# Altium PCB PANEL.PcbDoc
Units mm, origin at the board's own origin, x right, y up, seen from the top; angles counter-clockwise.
Board outline 203 x 188 mm, 4 copper layers (TOP, GND, SIG, BOTTOM), stack 1.586 mm thick; 0 components, 0 nets, 13 pads, 0 vias.
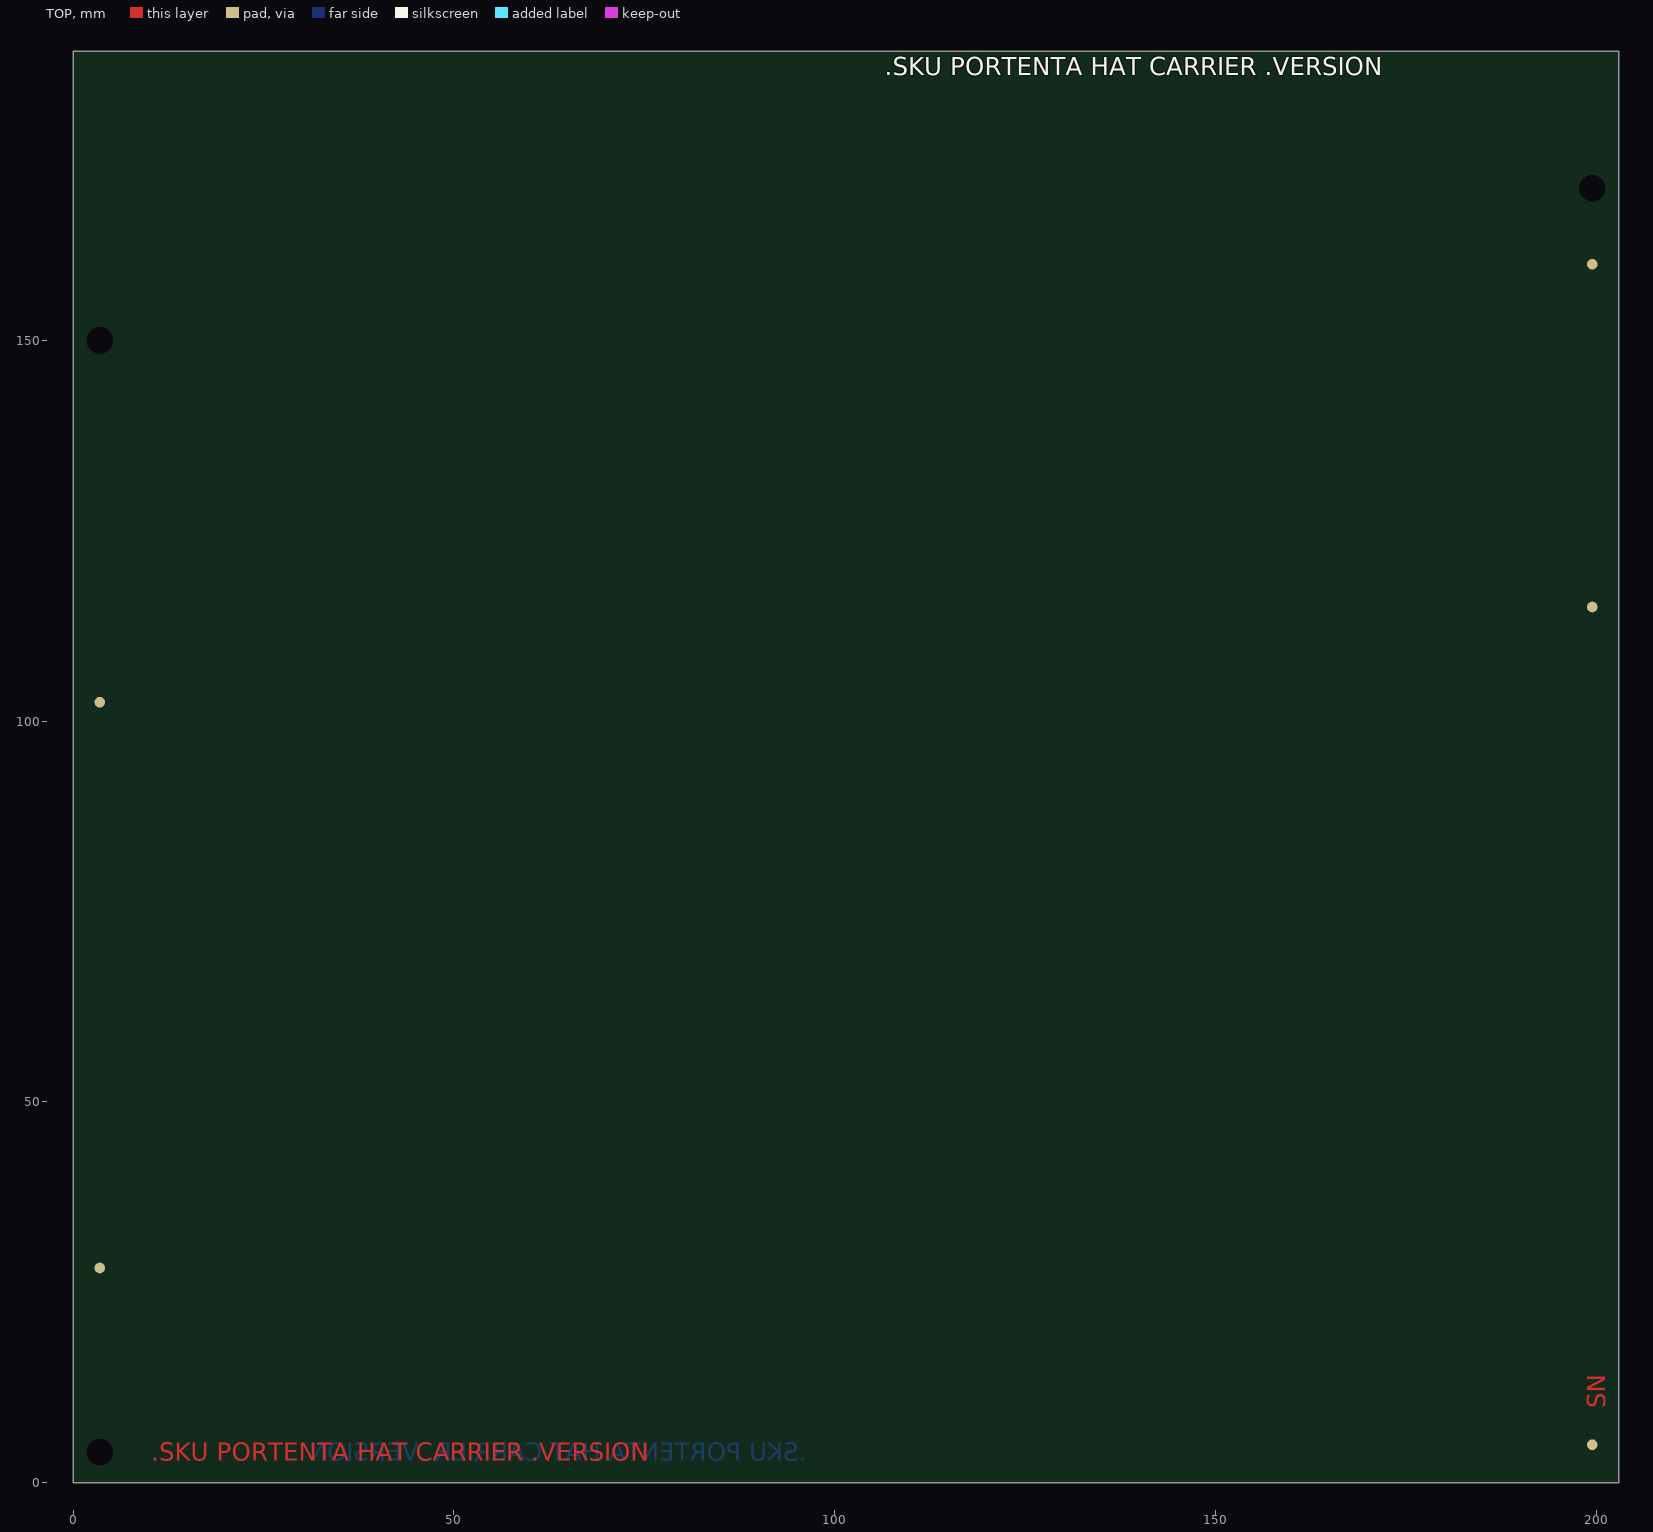
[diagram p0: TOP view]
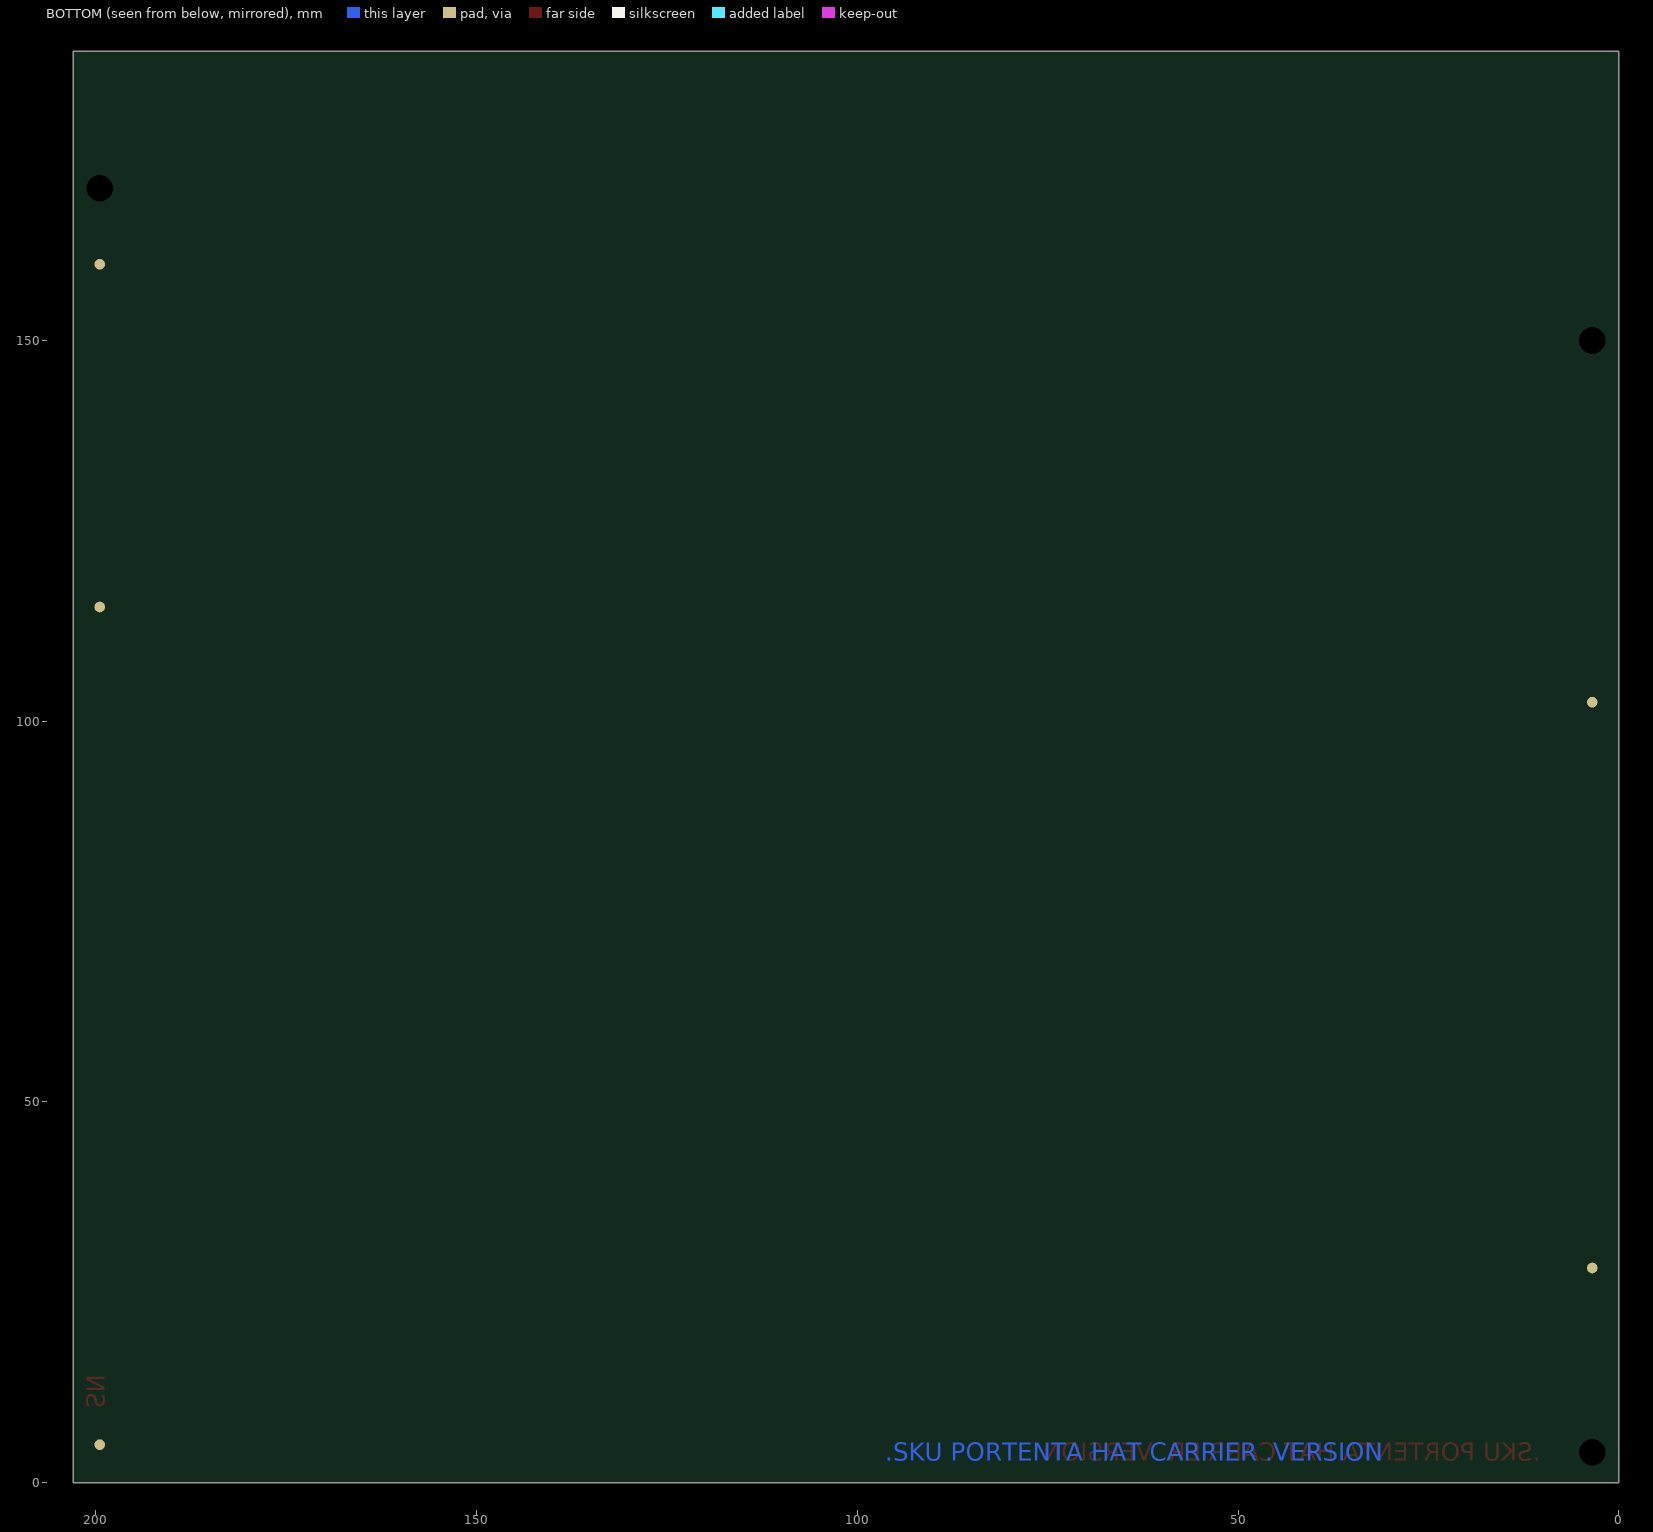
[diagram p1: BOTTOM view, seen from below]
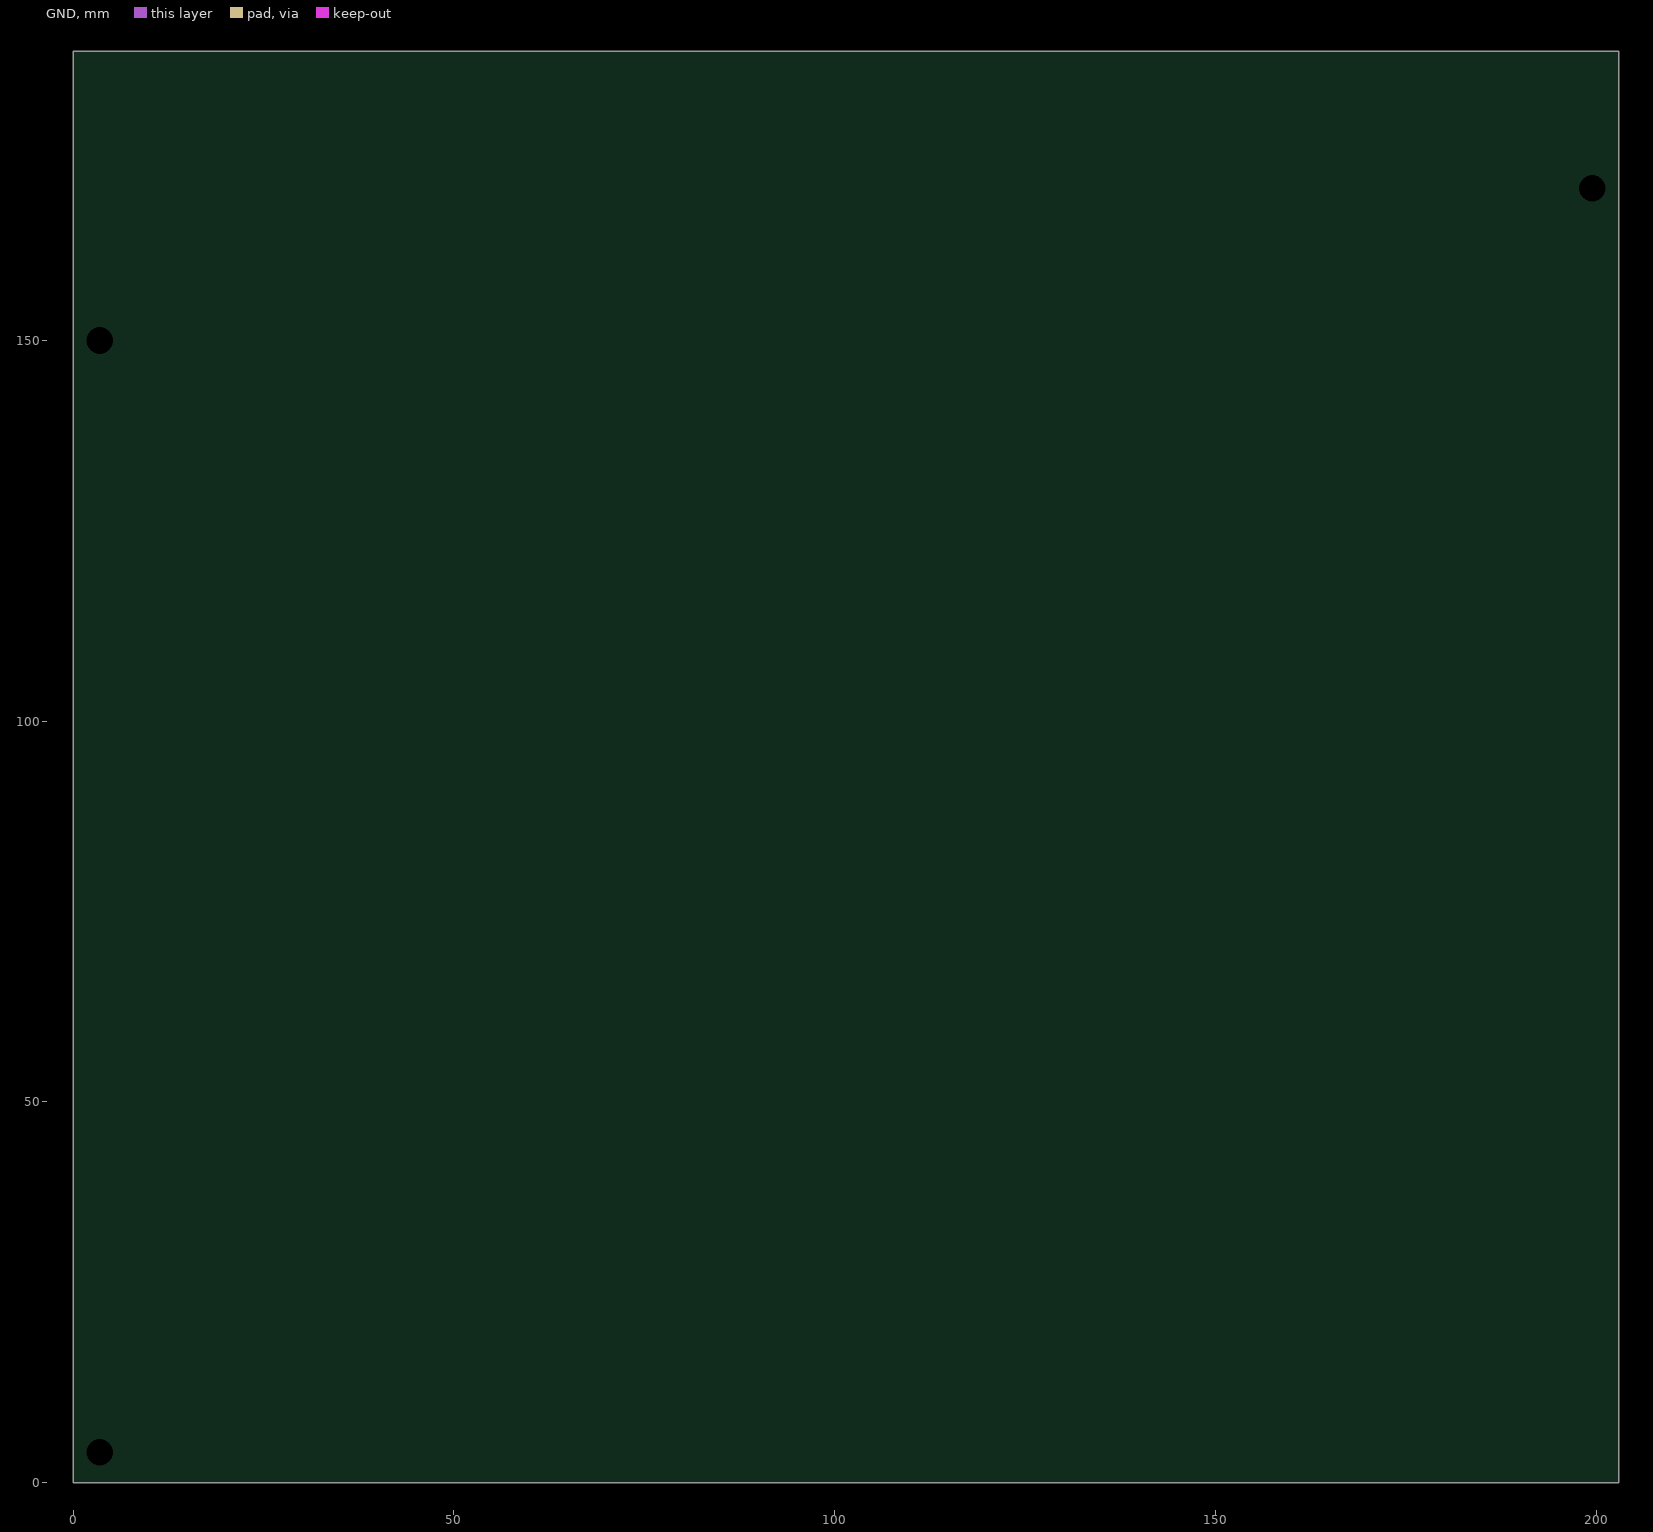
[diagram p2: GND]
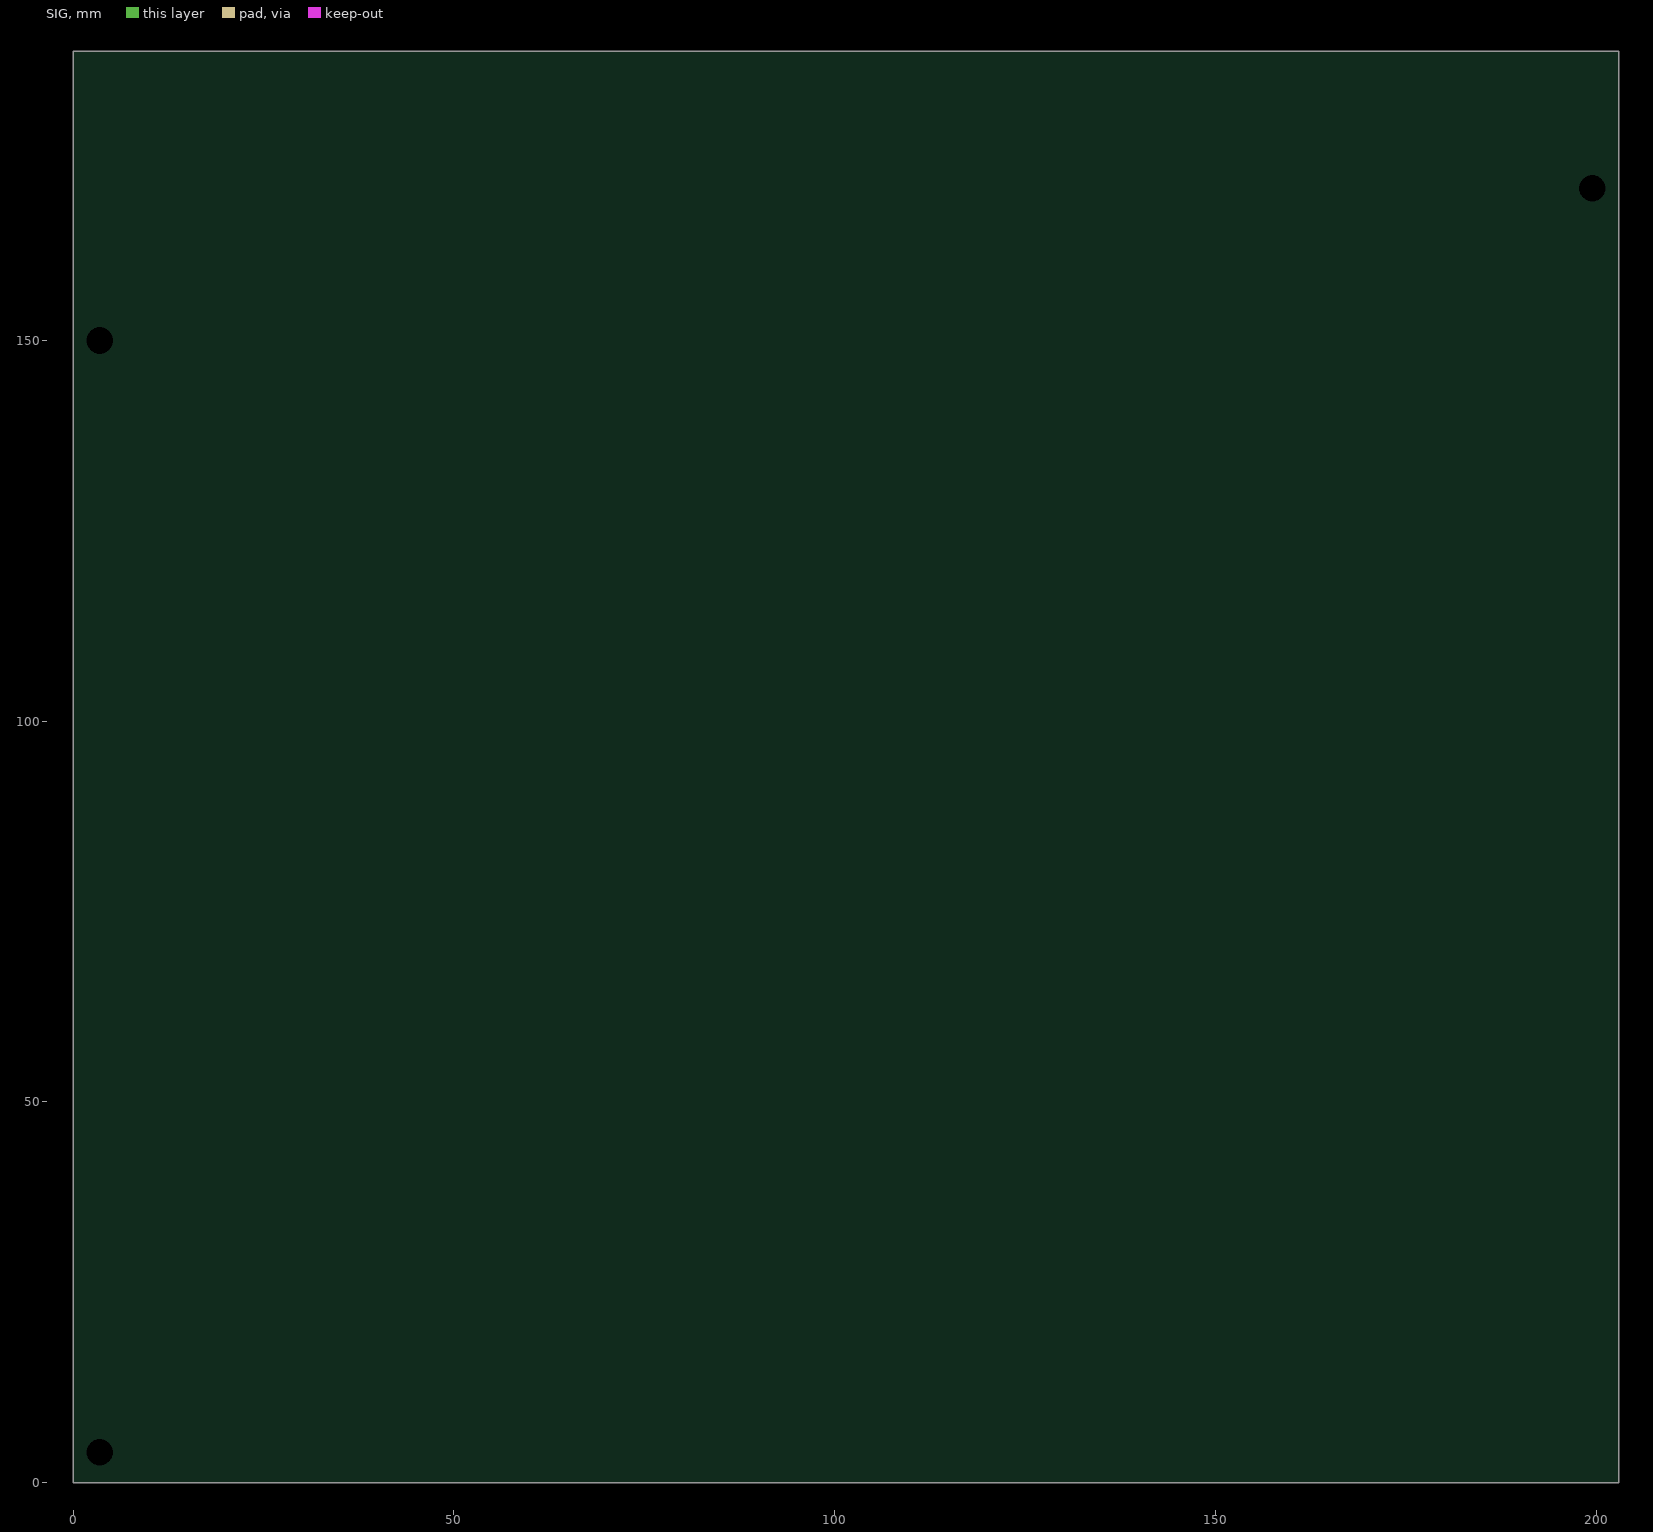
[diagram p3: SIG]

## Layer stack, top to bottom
Top Solder: solder mask 0.0102, Solder Resist, Dk 3.5
TOP: signal copper 0.018
Dielectric 1: prepreg 0.14, PP-014, Dk 4.2
GND: signal copper 0.035
Dielectric2: core 1.2, FR-4, Dk 4.8
SIG: signal copper 0.035
Dielectric3: prepreg 0.14, PP-014, Dk 4.2
BOTTOM: signal copper 0.018
Bottom Solder: solder mask 0.0102, Solder Resist, Dk 3.5

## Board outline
0,0 0,188 203,188 203,0

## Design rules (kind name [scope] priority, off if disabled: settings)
BoardOutlineClearance Silks [(OnLayer('Top Overlay') OR OnLayer('Bottom Overlay'))] p1: gap=0 ignorepadtopadclearanceinfootprint=FALSE
BoardOutlineClearance [All] p2: gap=0.3 ignorepadtopadclearanceinfootprint=FALSE
Clearance COPPER_0.3mm [All] p1: gap=0.127 ignorepadtopadclearanceinfootprint=FALSE except(0.3: Arc-Fill Arc-Poly Arc-Region Track-Fill Track-Poly Track-Region SMDPad-Fill SMDPad-Poly SMDPad-Region THPad-Fill THPad-Poly THPad-Region Via-Fill Via-Poly Via-Region Fill-Fill Fill-Poly Fill-Region Poly-Poly Poly-Region Region-Region)
Clearance "Generic clearance 0.127mm" [All] p2: gap=0.127 ignorepadtopadclearanceinfootprint=FALSE
ComponentClearance [All] p1: gap=0.2 collisioncheckmode=3 verticalgap=0 showdistances=TRUE
DiffPairsRouting USB [InDifferentialPairClass('USB')] p1: maxlimit=0.254 minlimit=0.15 mostfreqgap=0.254 toplayer_maxgap=0.15 toplayer_prefgap=0.15 toplayer_minwidth=0.15 toplayer_maxwidth=0.21 toplayer_prefwidth=0.2 midlayer2_mingap=0.24 midlayer2_maxgap=0.24 midlayer2_prefgap=0.24 midlayer2_minwidth=0.15 midlayer2_maxwidth=0.15 midlayer2_prefwidth=0.15 bottomlayer_maxgap=0.15 bottomlayer_prefgap=0.15 bottomlayer_minwidth=0.15 bottomlayer_maxwidth=0.21 bottomlayer_prefwidth=0.2 impedanceprofiledriven=TRUE impedanceprofileid={E6B00C31-4C8E-439C-824F-D2B2CDC26F9C} impedanceprofilevalue=90.000000 maxuncoupledlength=12.7
Height [All] p1: minheight=0 maxheight=30 prefheight=12.7
HoleSize [All] p1: absolutevalues=TRUE maxlimit=30 minlimit=0.3 maxpercent=80.000 minpercent=20.000
HoleToHoleClearance [All] p1: gap=0.25 allowstackedmicrovias=FALSE
MinimumAnnularRing [All] p1: minimumring=0.15
PlaneConnect [All] p1: pad.planeconnectstyle=Relief pad.reliefexpansion=0.508 pad.reliefentries=4 pad.reliefconductorwidth=0.254 pad.reliefairgap=0.254 via.planeconnectstyle=Direct via.reliefexpansion=0.508 via.reliefentries=4 via.reliefconductorwidth=0.254 via.reliefairgap=0.254
PolygonConnect [All] p1: thpad.connectstyle=Relief thpad.reliefconductorwidth=0.2 thpad.reliefentries=4 thpad.polygonreliefangle="90 Angle" thpad.airgapwidth=0.254 smdpad.connectstyle=Relief smdpad.reliefconductorwidth=0.2 smdpad.reliefentries=4 smdpad.polygonreliefangle="90 Angle" smdpad.airgapwidth=0.254 via.connectstyle=Direct via.reliefconductorwidth=0.254 via.reliefentries=4 via.polygonreliefangle="90 Angle" via.airgapwidth=0.254
RoutingVias StandardVias [All] p1: holewidth=0.3 width=0.6 viastyle="Through Hole" minholewidth=0.3 minwidth=0.6 maxholewidth=0.3 maxwidth=0.6
SMDToCorner [All] p1: distance=39370
SilkToSilkClearance [All] p1: silktosilkclearance=0.2
SilkToSolderMaskClearance [IsPad] p1: minsilkscreentomaskgap=0.15 clearancetoexposedcopper=TRUE
SolderMaskExpansion VIAtented [IsVia] p1: expansion=0.102 istentingtop=TRUE
SolderMaskExpansion [All] p2: expansion=0.05 istentingtop=FALSE
UnConnectedPin [All] p1:
UnRoutedNet [All] p1: checkbadconnections=TRUE
ViasUnderSMD [All] p1: allowed=FALSE
Width StandardTraces [All] p1: maxlimit=5 minlimit=0.127 preferedwidth=0.15
21 further rules are at their usual default settings.

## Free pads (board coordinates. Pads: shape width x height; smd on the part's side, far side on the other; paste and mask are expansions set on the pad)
  round 1.4 smd paste-5 mask+1.8: 21(3.5,28.2) 21(3.5,102.5) 21(199.5,5) 21(199.5,115) 21(199.5,160)
  round 1.4 smd far side paste-5 mask+1.8: 21(3.5,28.2) 21(3.5,102.5) 21(199.5,5) 21(199.5,115) 21(199.5,160)
  round 0 hole 3.5: 22(3.5,4) 22(3.5,150) 22(199.5,170)

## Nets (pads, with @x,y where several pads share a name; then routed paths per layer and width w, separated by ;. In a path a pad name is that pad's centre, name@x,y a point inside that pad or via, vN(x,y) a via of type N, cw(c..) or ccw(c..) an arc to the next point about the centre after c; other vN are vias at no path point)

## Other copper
TOP:
  text "TOP LAYER" at -52,72.784 h3
  text "SN" at 202,9.8 h4 r90
  text ".SKU PORTENTA HAT CARRIER .VERSION" at 10.272,2.102 h4
GND:
  text "LAYER 2" at -52,66.784 h3
SIG:
  text "LAYER 3" at -52,60.784 h3
BOTTOM:
  text "BOTTOM LAYER" at -52,54.784 h3
  text ".SKU PORTENTA HAT CARRIER .VERSION" at 96.328,2.102 h4

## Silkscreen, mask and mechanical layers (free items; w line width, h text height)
Top Overlay:
  text ".SKU PORTENTA HAT CARRIER .VERSION" at 106.587,184.046 h4
  text "TOP SILK" at -52,36.784 h3
Bottom Overlay:
  text "BOTTOM SILK" at -52,30.784 h3
Top Paste:
  text "TOP PASTE" at -52,24.784 h3
Bottom Paste:
  text "BOTTOM PASTE" at -52,18.784 h3
Top Solder:
  text "TOP SOLDER" at -52,48.784 h3
  text "SN" at 202,9.8 h4 r90
  text ".SKU PORTENTA HAT CARRIER .VERSION" at 10.272,2.102 h4
Bottom Solder:
  text "BOTTOM SOLDER" at -52,42.784 h3
  text ".SKU PORTENTA HAT CARRIER .VERSION" at 96.328,2.102 h4
Route Tool Path:
  text "ROUTE TOOL PATH" at -52,6.784 h3
Board:
  the board outline again, w0.1
  text "OUTLINE" at -52,12.784 h3
SCORING:
  lines w0.1: 8.9,0 8.9,188 ; 94.1,188 94.1,0 ; 105.9,0 105.9,188 ; 191.1,0 191.1,188
  text "SCORING" at -52,1 h3

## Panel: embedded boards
"PCB.PcbDoc" at 9,9, 3 rows x 2 columns, spacing 58 x 97, rotation 0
